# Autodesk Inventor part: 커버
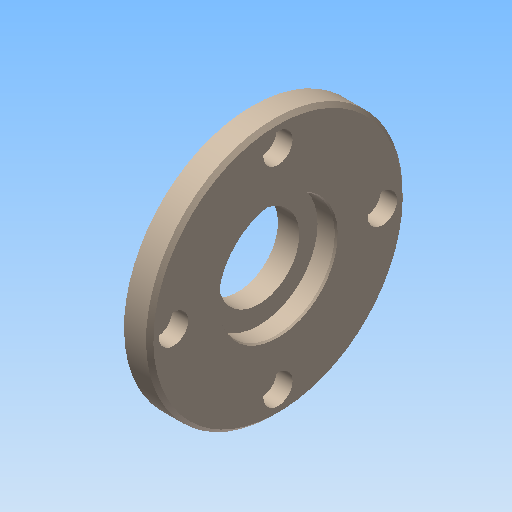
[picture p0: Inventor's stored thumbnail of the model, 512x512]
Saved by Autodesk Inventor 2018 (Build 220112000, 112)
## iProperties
Created: 2024-02
Part Number: 커버
Material: 알루미늄 6061
Document SubType Name: Modeling
Designer: mdu-01
Density: 1 g/cm^3
Appearance: 기본값(1)
Author: mdu-01
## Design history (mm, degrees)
sketch "스케치1"
  geometry: L1 (0, 0)-(12, 0); L2 (0, 20.5)-(0, 22.5); L3 (1, 23.5)-(5, 23.5); L4 (5, 23.5)-(5, 35); L5 (5, 35)-(11, 35); L6 (12, 34)-(12, 16.289); L7 (11.5, 16)-(6.8, 16); L8 (6.8, 16)-(6.8, 11); L9 (6.8, 11)-(1, 11); L10 (1, 11)-(1, 20.5); L11 (1, 20.5)-(0, 20.5); L12 (11.5, 16)-(12, 16.289); L13 (0, 22.5)-(1, 23.5); L14 (11, 35)-(12, 34); 3 further points
  constraints: 28 end point, 8 parallel, 8 point on line, 2 perpendicular, 1 horizontal
  dimensions: "d0" = 12 distance of L1.start L1.end; "d1" = 70 diameter of L5 L1; "d2" = 5 distance between parallel lines of L4 L2; "d3" = 47 diameter of L3 L1; "d4" = 41 diameter of L11 L1; "d5" = 22 diameter of L9 L1; "d6" = 32 diameter of L7 L1; "d7" = 1 distance between parallel lines of L2 L10; "d8" = 5.2 distance between parallel lines of L6 L8; "d10" = 0.5 distance of L7.start point (12, 16); "d11" = 30 deg angle of L7 L12; "d12" = 1 distance of L2.end point (0, 23.5); "d13" = 1 distance of L3.start point (0, 23.5) (= d12); "d14" = 1 distance of L5.end point (12, 35); "d15" = 1 distance of L6.start point (12, 35) (= d14)
revolve "회전1" sketch "스케치1" stored, may be unused: angle "d16" = 90 deg
sketch "스케치2" dims "d17" = 57
  geometry: 3 further points
  constraints: 2 vertical alignment, 1 coincident, 2 other
hole "구멍1" sketch "스케치2" at (0, 28.5) diameter "d18" = 4.5; stored, may be unused: countersink angle "d22" = 90 deg, drill point angle "d24" = 118 deg; dims "d19" = 6, "d20" = 8, "d21" = 4.4, "d23" = 8
node "솔리드1"
pattern_circular "원형 패턴1" dims angle "d26" = 360 deg
